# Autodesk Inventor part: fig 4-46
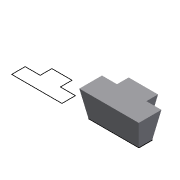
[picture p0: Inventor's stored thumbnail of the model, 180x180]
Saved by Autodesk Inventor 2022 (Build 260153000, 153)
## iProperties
Created: 2004-05
Part Number: fig 4-46
Document SubType Name: Modeling
Designer: CADCIM Technologies
Manufacturer: Standard
Standards Organization: Custom
Density: 1 g/cm^3
Material: Generic
Appearance: Default
Author: CADCIM Technologies
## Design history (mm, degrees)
sketch "Sketch1"
  geometry: L1 (31.783, 34.561)-(31.783, 22.933); L2 (31.783, 22.933)-(16.796, 22.933); L3 (16.796, 22.933)-(16.796, 9.496); L4 (16.796, 9.496)-(66.925, 9.496); L5 (66.925, 9.496)-(66.925, 22.933); L6 (66.925, 22.933)-(51.938, 22.933); L7 (51.938, 22.933)-(51.938, 34.561); L8 (51.938, 34.561)-(31.783, 34.561); L9 (-45.013, 34.561)-(-45.013, 22.933); L10 (-45.013, 22.933)-(-60, 22.933); L11 (-60, 22.933)-(-60, 9.496); L12 (-60, 9.496)-(-9.871, 9.496); L13 (-9.871, 9.496)-(-9.871, 22.933); L14 (-9.871, 22.933)-(-24.858, 22.933); L15 (-24.858, 22.933)-(-24.858, 34.561); L16 (-24.858, 34.561)-(-45.013, 34.561)
  constraints: 32 end point, 10 parallel, 4 equal length, 2 collinear, 2 perpendicular, 2 vertical
extrude "Extrusion2" new body sketch "Sketch1" distance "d2" = 26; taper "d3" = 10 deg
body "Solid2"
